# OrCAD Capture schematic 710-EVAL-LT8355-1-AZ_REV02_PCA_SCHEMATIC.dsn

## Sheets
1 PAGE2 - LT8355-1 CH2: size Custom; note: DEMO BOARD BILL OF MATERIALS; note: HIGH VOLTAGE DUAL LED CONTROLLER
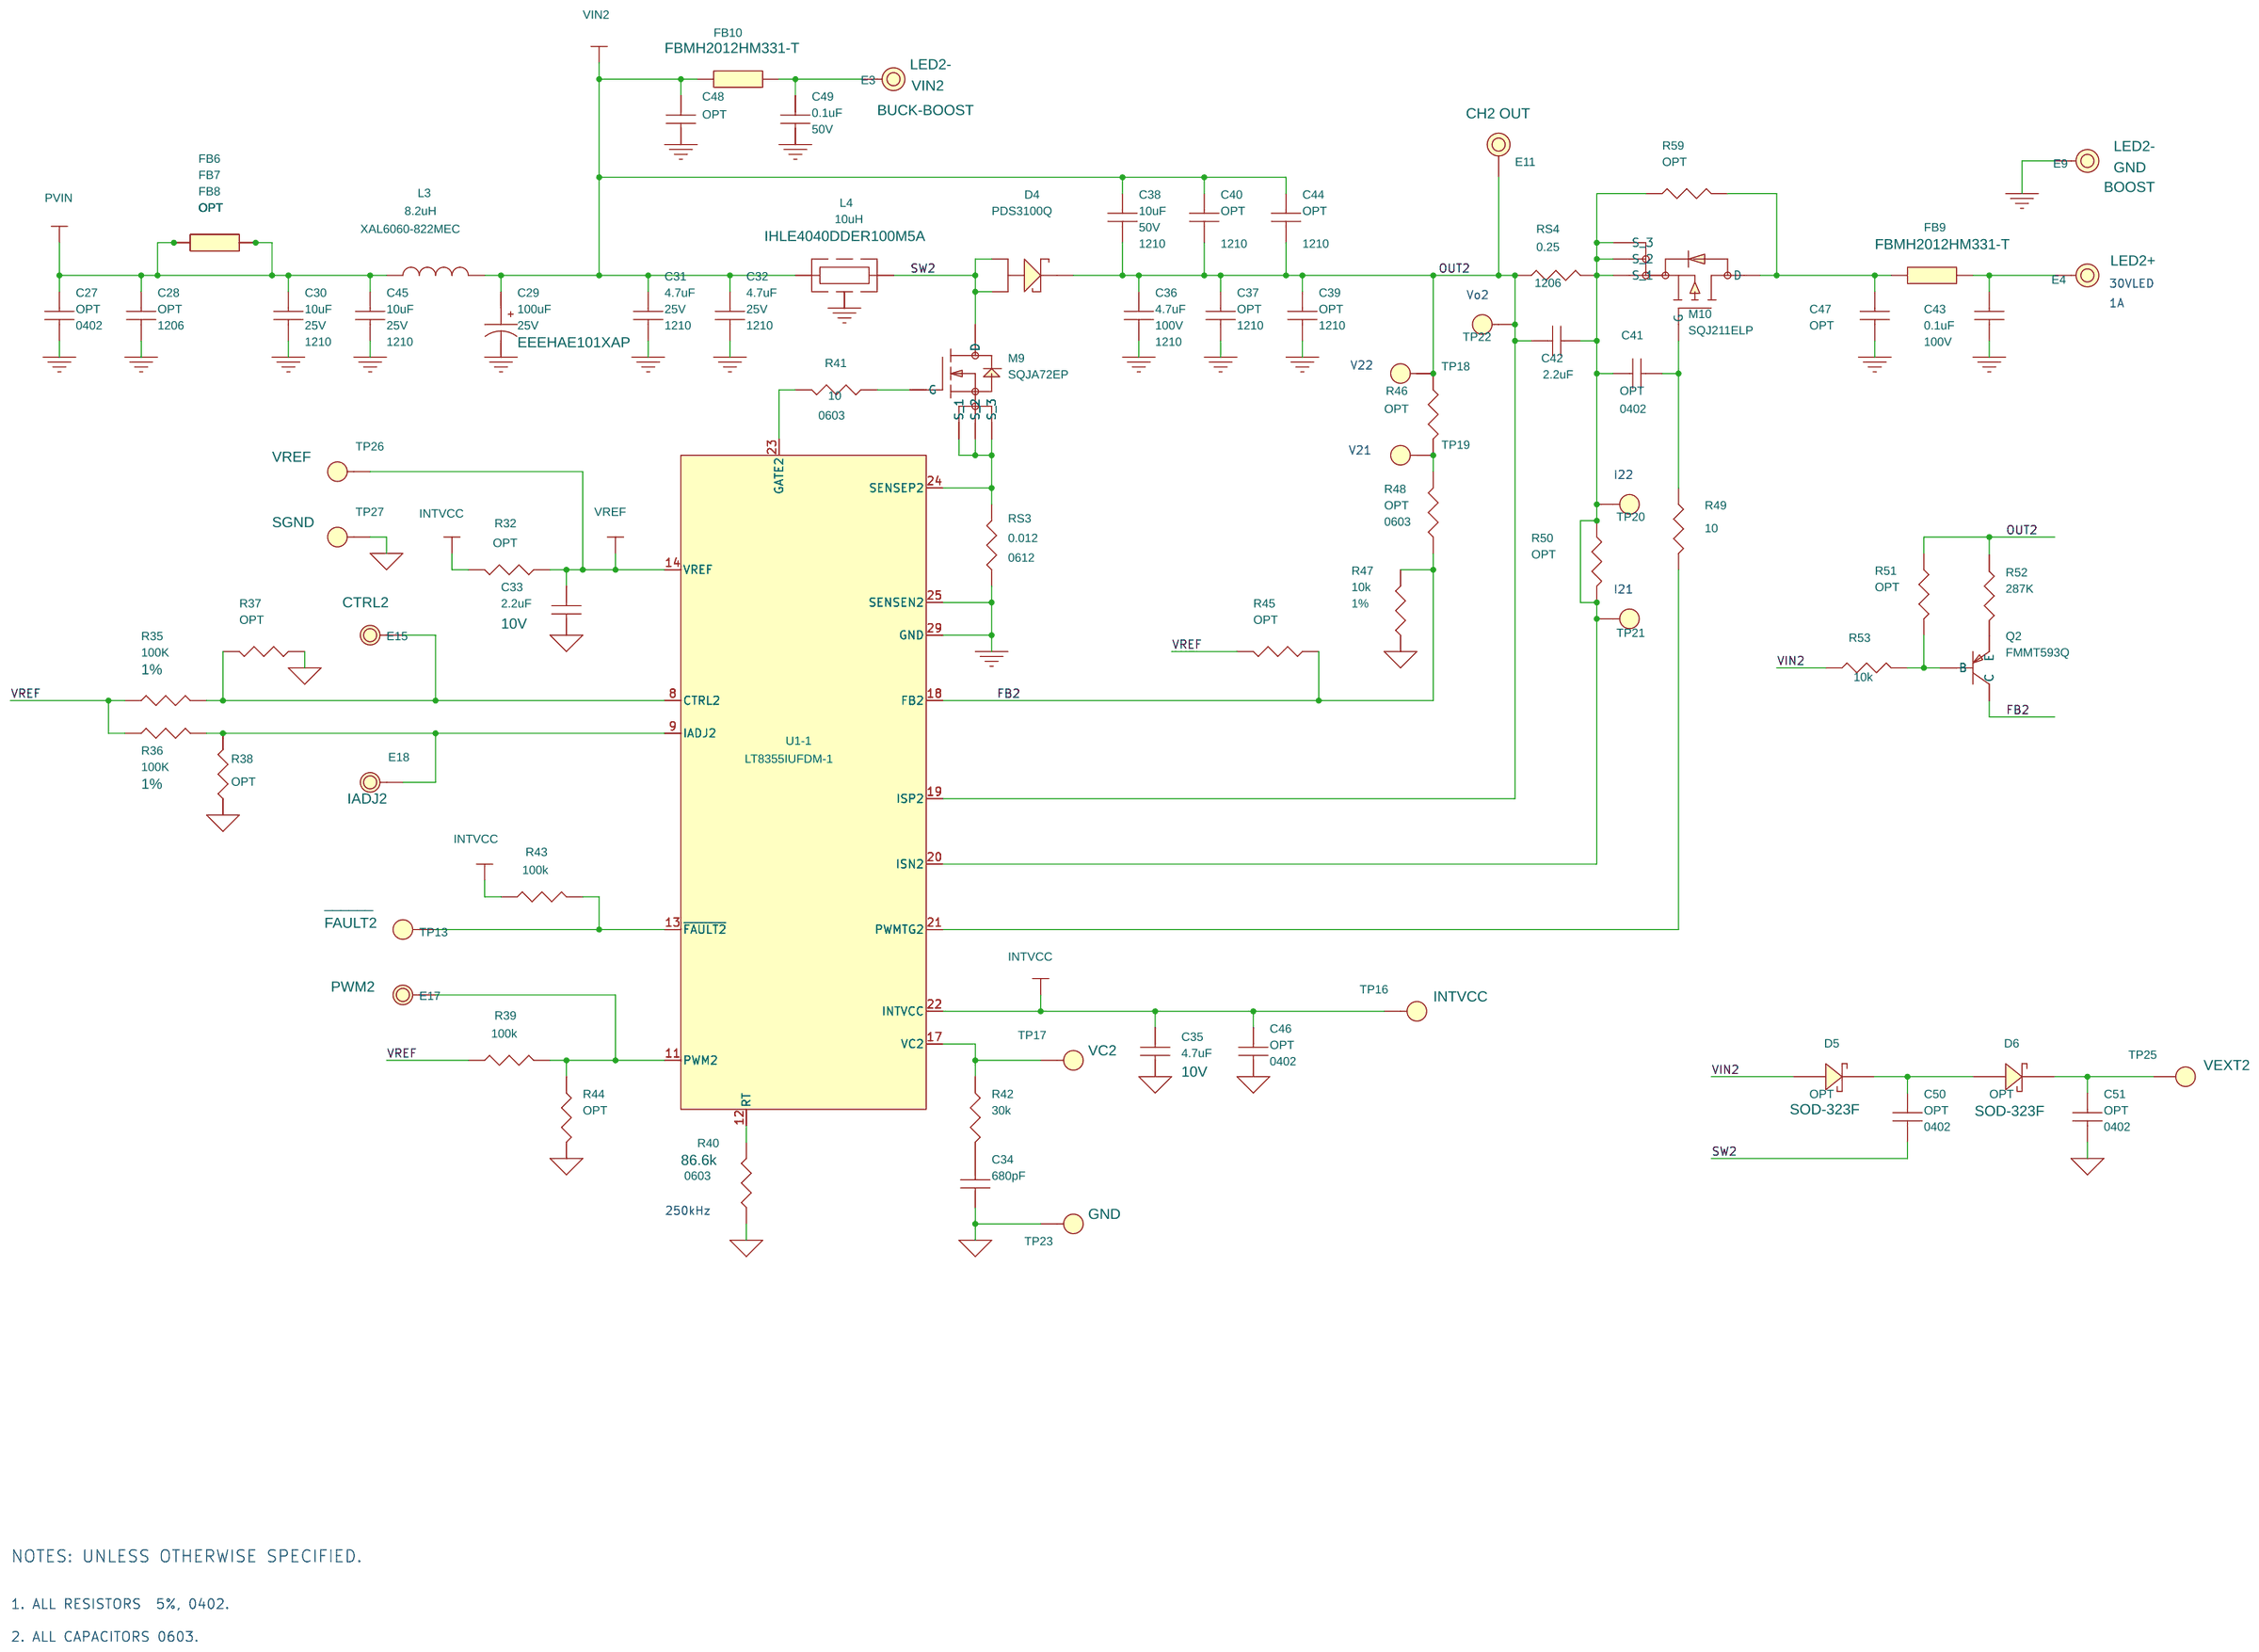
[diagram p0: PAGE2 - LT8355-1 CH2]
2 PAGE3 - HW
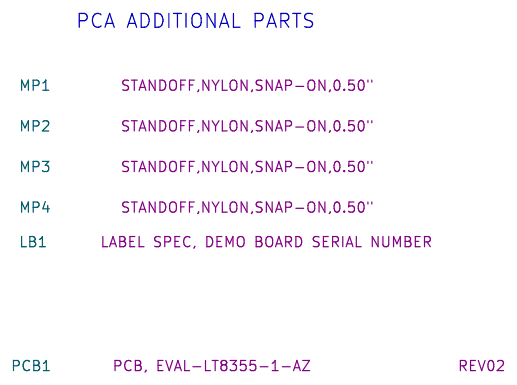
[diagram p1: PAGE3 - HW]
3 PAGE1 - LT8355-1 CH1: size Custom
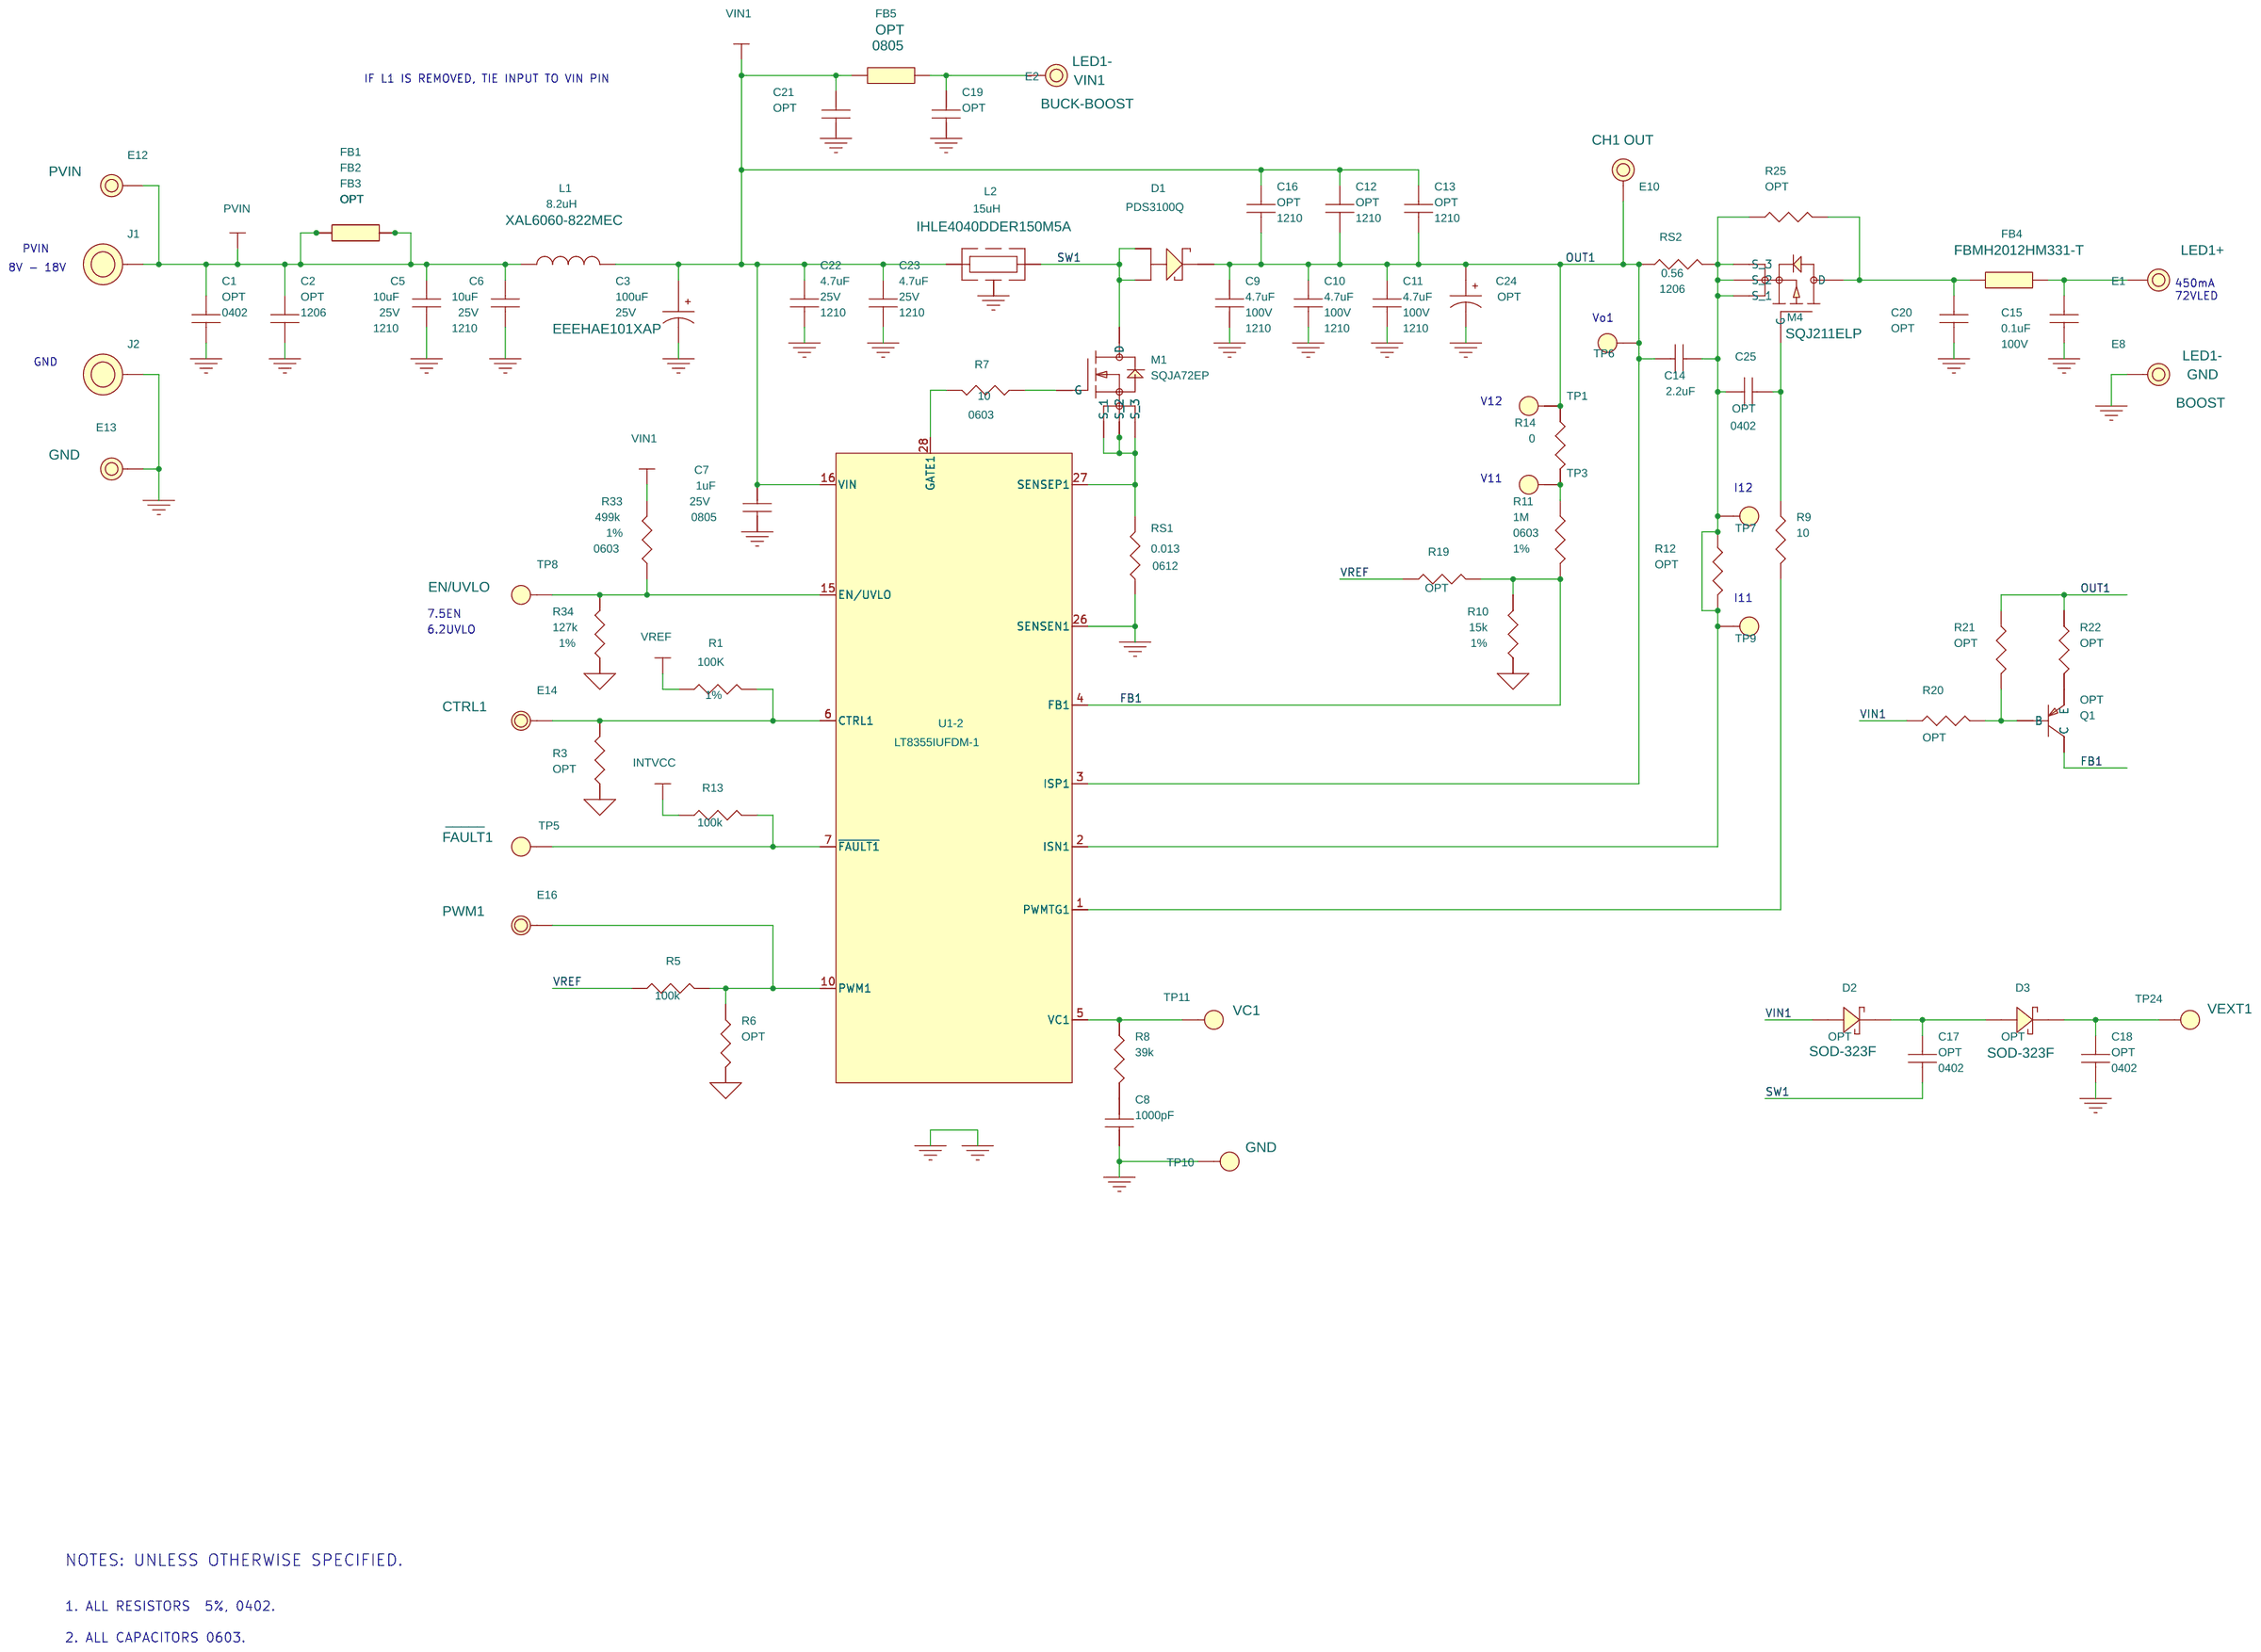
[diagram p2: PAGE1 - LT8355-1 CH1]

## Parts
sheet PAGE1 - LT8355-1 CH1
C1  OPT  [CC0402N]
C2  OPT  [CC1206N]
C3  100uF  [PANASONIC_HA_6.3X7.7]
C5  10uF  [CC1210N]
C6  10uF  [CC1210N]
C7  1uF  [CC0805N]
C8  1000pF  [CC0402N]
C9  4.7uF  [CC1210N]
C10  4.7uF  [CC1210N]
C11  4.7uF  [CC1210N]
C12  OPT  [CC1210N]
C13  OPT  [CC1210N]
C14  2.2uF  [CC0603N]
C15  0.1uF  [CC0603N]
C16  OPT  [CC1210N]
C17  OPT  [CC0402N]
C18  OPT  [CC0402N]
C19  OPT  [CC0603N]
C20  OPT  [CC0603N]
C21  OPT  [CC0603N]
C22  4.7uF  [CC1210N]
C23  4.7uF  [CC1210N]
C24  OPT  [CAP_OPT_8]
C25  OPT  [CC0402N]
D1  PDS3100Q  [POWERDI-5]
D2  OPT  [SOD-323F-N]
D3  OPT  [SOD-323F-N]
E1  TEST POINT  [MILLMAX2501]
E2  TEST POINT  [MILLMAX2501]
E8  TEST POINT  [MILLMAX2501]
E10  TEST POINT  [MILLMAX2501]
E12  TEST POINT  [MILLMAX2501]
E13  TEST POINT  [MILLMAX2501]
E14  TEST POINT  [MILLMAX2308]
E16  TEST POINT  [MILLMAX2308]
FB1  OPT  [IND1210N]
FB2  OPT  [IND1210N]
FB3  OPT  [IND1210N]
FB4  330 OHMS@100MHz  [IND0805N]
FB5  OPT  [IND0805N]
J1  BANANA JACK  [KEY-575-4]
J2  BANANA JACK  [KEY-575-4]
L1  8.2uH  [COILCRAFT-XAL6060]
L2  15uH  [VISHAY-IHLE-4040DD-5A]
M1  SQJA72EP  [VISHAY_PPAK-SO-8L]
M4  SQJ211ELP  [VISHAY_PPAK-SO-8L]
Q1  OPT  [SOT23-3N]
R1  100K  [CR0402N]
R3  OPT  [CR0402N]
R5  100k  [CR0402N]
R6  OPT  [CR0402N]
R7  10  [CR0603N]
R8  39k  [CR0402N]
R9  10  [CR0402N]
R10  15k  [CR0402N]
R11  1M  [CR0603N]
R12  OPT  [CR0402N]
R13  100k  [CR0402N]
R14  0  [CR0402N]
R19  OPT  [CR0402N]
R20  OPT  [CR0402N]
R21  OPT  [CR0402N]
R22  OPT  [CR0402N]
R25  OPT  [CR0402N]
R33  499k  [CR0603N]
R34  127k  [CR0402N]
RS1  0.013  [ROHM-LTR18]
RS2  0.56  [CR1206N]
TP1  TEST PAD  [PADSTYLE1]
TP3  TEST PAD  [PADSTYLE1]
TP5  TEST PAD  [PADSTYLE1]
TP6  TEST PAD  [PADSTYLE1]
TP7  TEST PAD  [PADSTYLE1]
TP8  TEST PAD  [PADSTYLE1]
TP9  TEST PAD  [PADSTYLE1]
TP10  TEST PAD  [PADSTYLE1]
TP11  TEST PAD  [PADSTYLE1]
TP24  TEST PAD  [PADSTYLE1]
sheet PAGE2 - LT8355-1 CH2
C27  OPT  [CC0402N]
C28  OPT  [CC1206N]
C29  100uF  [PANASONIC_HA_6.3X7.7]
C30  10uF  [CC1210N]
C31  4.7uF  [CC1210N]
C32  4.7uF  [CC1210N]
C33  2.2uF  [CC0603N]
C34  680pF  [CC0402N]
C35  4.7uF  [CC0603N]
C36  4.7uF  [CC1210N]
C37  OPT  [CC1210N]
C38  10uF  [CC1210N]
C39  OPT  [CC1210N]
C40  OPT  [CC1210N]
C41  OPT  [CC0402N]
C42  2.2uF  [CC0603N]
C43  0.1uF  [CC0603N]
C44  OPT  [CC1210N]
C45  10uF  [CC1210N]
C46  OPT  [CC0402N]
C47  OPT  [CC0603N]
C48  OPT  [CC0603N]
C49  0.1uF  [CC0603N]
C50  OPT  [CC0402N]
C51  OPT  [CC0402N]
D4  PDS3100Q  [POWERDI-5]
D5  OPT  [SOD-323F-N]
D6  OPT  [SOD-323F-N]
E3  TEST POINT  [MILLMAX2501]
E4  TEST POINT  [MILLMAX2501]
E9  TEST POINT  [MILLMAX2501]
E11  TEST POINT  [MILLMAX2501]
E15  TEST POINT  [MILLMAX2308]
E17  TEST POINT  [MILLMAX2308]
E18  TEST POINT  [MILLMAX2308]
FB6  OPT  [IND1210N]
FB7  OPT  [IND1210N]
FB8  OPT  [IND1210N]
FB9  330 OHMS@100MHz  [IND0805N]
FB10  330 OHMS@100MHz  [IND0805N]
L3  8.2uH  [COILCRAFT-XAL6060]
L4  10uH  [VISHAY-IHLE-4040DD-5A]
M9  SQJA72EP  [VISHAY_PPAK-SO-8L]
M10  SQJ211ELP  [VISHAY_PPAK-SO-8L]
Q2  FMMT593Q  [SOT23-3N]
R32  OPT  [CR0402N]
R35  100K  [CR0402N]
R36  100K  [CR0402N]
R37  OPT  [CR0402N]
R38  OPT  [CR0402N]
R39  100k  [CR0402N]
R40  86.6k  [CR0603N]
R41  10  [CR0603N]
R42  30k  [CR0402N]
R43  100k  [CR0402N]
R44  OPT  [CR0402N]
R45  OPT  [CR0402N]
R46  OPT  [CR0402N]
R47  10k  [CR0402N]
R48  OPT  [CR0603N]
R49  10  [CR0402N]
R50  OPT  [CR0402N]
R51  OPT  [CR0402N]
R52  287K  [CR0402N]
R53  10k  [CR0402N]
R59  OPT  [CR0402N]
RS3  0.012  [KOA-WU73-2B15]
RS4  0.25  [CR1206N]
TP13  TEST PAD  [PADSTYLE1]
TP16  TEST PAD  [PADSTYLE1]
TP17  TEST PAD  [PADSTYLE1]
TP18  TEST PAD  [PADSTYLE1]
TP19  TEST PAD  [PADSTYLE1]
TP20  TEST PAD  [PADSTYLE1]
TP21  TEST PAD  [PADSTYLE1]
TP22  TEST PAD  [PADSTYLE1]
TP23  TEST PAD  [PADSTYLE1]
TP25  TEST PAD  [PADSTYLE1]
TP26  TEST PAD  [PADSTYLE1]
TP27  TEST PAD  [PADSTYLE1]
U1  LT8355IUFDM-1  [LTC-UFDM-28-1682]  (sections -1,-2)
sheet PAGE3 - HW
LB1  LABEL  [895-0154_REV01]
MP1  STANDOFF  [KEYSTONE_8829-8834]
MP2  STANDOFF  [KEYSTONE_8829-8834]
MP3  STANDOFF  [KEYSTONE_8829-8834]
MP4  STANDOFF  [KEYSTONE_8829-8834]
PCB1  PCB, EVAL-LT8355-1-AZ

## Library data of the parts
C1 C17 C18 C25 C27 C41 C46 C50 C51 = CAP: CAP., OPTION, 0402; CLASS: DISCRETE; FPLIST: CC0402N,CC0402L,CC0402M; PART_NUMBER: 150-3148; Package Size: 0402; Package Type: SMD
C2 C28 = CAP: CAP., OPTION, 1206; CLASS: DISCRETE; FPLIST: CC1206N,CC1206L,CC1206M; PART_NUMBER: 150-3160; Package Size: 1206; Package Type: SMD
C3 C29 = CAP_P_ALT: CAP.,100uF,ALUM ELECT,25V,20%,,6.3x7.7mm,D8,SMD,RADIAL,EEEHA,AEC-Q200; CLASS: DISCRETE; Dielectric Type: ALUM ELECT; Inventory Qty: 0; Manufacturer: PANASONIC; Manufacturer PN: EEEHAE101XAP; PART_NUMBER: 150-1898; Package Size: ,6.3x7.7mm,D8,SMD,RADIAL; Rated Voltage: 25V; Tolerance: 20%
C5 C6 C30 C45 = CAP: CAP.,10uF,X7R,25V,10%,1210,AEC-Q200; CLASS: DISCRETE; Dielectric Type: X7R; FPLIST: CC1210N,CC1210L,CC1210M; Inventory Qty: 0; Manufacturer: TDK; Manufacturer PN: CGA6P1X7R1E106K250AC; PART_NUMBER: 150-1852; Package Size: 1210; Rated Voltage: 25V; Temperature Coefficient: X7R; Tolerance: 10%
C7 = CAP: CAP.,1uF,X7R,25V,10%,0805,AEC-Q200; CLASS: DISCRETE; Dielectric Type: X7R; FPLIST: CC0805N,CC0805L,CC0805M; Inventory Qty: 1975; Manufacturer: TDK; Manufacturer PN: CGA4J3X7R1E105K125AB; PART_NUMBER: 150-0504; Package Size: 0805; Rated Voltage: 25V; Tolerance: 10%
C8 = CAP: CAP.,1000pF,X7R,50V,10%,0402,AEC-Q200; CLASS: DISCRETE; Dielectric Type: X7R; FPLIST: CC0402N,CC0402L,CC0402M; Inventory Qty: 12960; Manufacturer: MURATA; Manufacturer PN: GCM155R71H102KA37D; PART_NUMBER: 150-1752; Package Size: 0402; Package Type: SMD; Rated Voltage: 50V; Tolerance: 10%
C9-C11 C36 = CAP: CAP.,4.7uF,X7S,100V,10%,1210,AEC-Q200; CLASS: DISCRETE; Dielectric Type: X7S; FPLIST: CC1210N,CC1210L,CC1210M; Inventory Qty: 14180; Manufacturer: MURATA; Manufacturer PN: GCM32DC72A475KE02L; PART_NUMBER: 150-3376; Package Size: 1210; Rated Voltage: 100V; Tolerance: 10%
C12 C13 C16 C37 C39 C40 C44 = CAP: CAP., OPTION, 1210; CLASS: DISCRETE; FPLIST: CC1210N,CC1210L,CC1210M; PART_NUMBER: 150-3035; Package Size: 1210; Package Type: SMD
C14 C42 = CAP: CAP.,2.2uF,X5R,25V,10%,0603,AEC-Q200; CLASS: DISCRETE; Dielectric Type: X5R; FPLIST: CC0603N,CC0603L,CC0603M; Inventory Qty: 0; Manufacturer: TAIYO YUDEN; Manufacturer PN: TMK107BBJ225KAHT; PART_NUMBER: 150-0955; Package Size: 0603; Rated Voltage: 25V; Tolerance: 10%
C15 C43 = CAP: CAP.,0.1uF,X7S,100V,10%,0603,AEC-Q200; CLASS: DISCRETE; Dielectric Type: X7S; FPLIST: CC0603N,CC0603L,CC0603M; Inventory Qty: 27710; Manufacturer: TDK; Manufacturer PN: CGA3E3X7S2A104K080AB; PART_NUMBER: 150-2322; Package Size: 0603; Rated Voltage: 100V; Tolerance: 10%
C19-C21 C47 C48 = CAP: CAP., OPTION, 0603; CLASS: DISCRETE; FPLIST: CC0603N,CC0603L,CC0603M; PART_NUMBER: 150-3038; Package Size: 0603; Package Type: SMD
C22 C23 C31 C32 = CAP: CAP.,4.7uF,X7R,25V,10%,1210,AEC-Q200; CLASS: DISCRETE; Dielectric Type: X7R; FPLIST: CC1210N,CC1210L,CC1210M; Inventory Qty: 0; Manufacturer: Taiyo Yuden; Manufacturer PN: TMF325B7475KMHP; PART_NUMBER: 150-1899; Package Size: 1210; Package Type: SMD; Rated Voltage: 25V; Tolerance: 10%
C24 = CAP_P_ALT: CAP.,OPTION,ALUM. ELECT.,SMD; CLASS: DISCRETE; FPLIST: USER_ASSIGNED,USER_1,USER_2,USER_3,USER_4,USER_5,USER_6,USER_7,CAP_OPT_6.3,CAP_OPT_8,CAP_OPT_10,CAP_OPT_12.5,CAP_OPT_13,CAP_OPT_16,CAP_OPT_18; PART_NUMBER: 150-0497; Package Type: SMD
D1 D4 = DIODE_SCHOTTKY_POWERDI5: DIODE,SCHOTTKY,100V,3A,POWERDI5,AEC-Q101; CLASS: DISCRETE; FPLIST: POWERDI-5,POWERDI-5_2PIN; Inventory Qty: 0; Manufacturer: DIODES INC.; Manufacturer PN: PDS3100Q-13; Max Forward Current or Rated Power: 3A; PART_NUMBER: 210-0596; Package Type: PowerDI5; Rated Voltage or Zener Voltage: 100V
D2 D3 D5 D6 = DIODE_SCHOTTKY_A_ALT: DIODE,OPTION, SOD-323F; BOM Notes: BAT46WJ; CLASS: DISCRETE; FPLIST: SOD-323F-N,SOD-323F-L,SOD-323F-M; PART_NUMBER: 210-0458; Package Size: SOD-323F; Package Type: SOD323F-2
E1 = TESTPOINT_.219_MILL-MAX_2501: TEST POINT,TURRET,0.094" MTG. HOLE,PCB 0.062" THK; 10th Part Field: TURN+; 11th Part Field: 52V OVLO; 12th Part Field: 60V MAX.; 9th Part Field: LED1+; CLASS: IO; FPLIST: MILLMAX2501,MILLMAX2501-2; Inventory Qty: 823526; Manufacturer: MILL-MAX; Manufacturer PN: 2501-2-00-80-00-00-07-0; PART_NUMBER: 260-0003
E2 = TESTPOINT_.219_MILL-MAX_2501: TEST POINT,TURRET,0.094" MTG. HOLE,PCB 0.062" THK; 10th Part Field: VIN1; 11th Part Field: BUCK-BOOST; 12th Part Field: 60V MAX.; 9th Part Field: LED1-; CLASS: IO; FPLIST: MILLMAX2501,MILLMAX2501-2; Inventory Qty: 823526; Manufacturer: MILL-MAX; Manufacturer PN: 2501-2-00-80-00-00-07-0; PART_NUMBER: 260-0003
E8 = TESTPOINT_.219_MILL-MAX_2501: TEST POINT,TURRET,0.094" MTG. HOLE,PCB 0.062" THK; 10th Part Field: GND; 11th Part Field: BOOST; 12th Part Field: 60V MAX.; 9th Part Field: LED1-; CLASS: IO; FPLIST: MILLMAX2501,MILLMAX2501-2; Inventory Qty: 823526; Manufacturer: MILL-MAX; Manufacturer PN: 2501-2-00-80-00-00-07-0; PART_NUMBER: 260-0003
E10 = TESTPOINT_.219_MILL-MAX_2501: TEST POINT,TURRET,0.094" MTG. HOLE,PCB 0.062" THK; 10th Part Field: CH1 OUT; 11th Part Field: CH1 OUT; 12th Part Field: CH1 OUT; 9th Part Field: CH1 OUT; CLASS: IO; FPLIST: MILLMAX2501,MILLMAX2501-2; Inventory Qty: 823526; Manufacturer: MILL-MAX; Manufacturer PN: 2501-2-00-80-00-00-07-0; PART_NUMBER: 260-0003
E12 = TESTPOINT_.219_MILL-MAX_2501: TEST POINT,TURRET,0.094" MTG. HOLE,PCB 0.062" THK; 10th Part Field: TURN+; 11th Part Field: 52V OVLO; 12th Part Field: 60V MAX.; 9th Part Field: PVIN; CLASS: IO; FPLIST: MILLMAX2501,MILLMAX2501-2; Inventory Qty: 823526; Manufacturer: MILL-MAX; Manufacturer PN: 2501-2-00-80-00-00-07-0; PART_NUMBER: 260-0003
E13 = TESTPOINT_.219_MILL-MAX_2501: TEST POINT,TURRET,0.094" MTG. HOLE,PCB 0.062" THK; 10th Part Field: GND; 11th Part Field: 52V OVLO; 12th Part Field: 60V MAX.; 9th Part Field: GND; CLASS: IO; FPLIST: MILLMAX2501,MILLMAX2501-2; Inventory Qty: 823526; Manufacturer: MILL-MAX; Manufacturer PN: 2501-2-00-80-00-00-07-0; PART_NUMBER: 260-0003
E14 = TEST_POINT_.156_MILL-MAX_2308_A: TEST POINT,TURRET,0.064" MTG. HOLE,PCB 0.062" THK; 9th Part Field: CTRL1; CLASS: IO; FPLIST: MILLMAX2308,MILLMAX2308-2; Inventory Qty: 1142083; Manufacturer: MILL-MAX; Manufacturer PN: 2308-2-00-80-00-00-07-0; PART_NUMBER: 260-0004
E16 = TEST_POINT_.156_MILL-MAX_2308_A: TEST POINT,TURRET,0.064" MTG. HOLE,PCB 0.062" THK; 9th Part Field: PWM1; CLASS: IO; FPLIST: MILLMAX2308,MILLMAX2308-2; Inventory Qty: 1142083; Manufacturer: MILL-MAX; Manufacturer PN: 2308-2-00-80-00-00-07-0; PART_NUMBER: 260-0004
FB1-FB3 FB6-FB8 = FERRITEBEAD_ALT1: IND.,OPTION,FERRITE BEAD,1210; CLASS: DISCRETE; FPLIST: IND1210N,IND1210L,IND1210M; PART_NUMBER: 200-0785; Package Size: 1210
FB4 FB9 FB10 = FERRITEBEAD_ALT1: IND.,330 OHMS@100MHz,FERRITE BEAD,25%,1.8A,80mOHMS,0805,1LN; CLASS: DISCRETE; FPLIST: IND0805N,IND0805L,IND0805M; Inventory Qty: 4000; Manufacturer: TAIYO YUDEN; Manufacturer PN: FBMH2012HM331-T; PART_NUMBER: 200-0778; Package Size: 0805; Tolerance: 25%
FB5 = FERRITEBEAD_ALT1: IND.,FERRITE BEAD,OPT,0805; CLASS: DISCRETE; FPLIST: IND0805N,IND0805L,IND0805M; PART_NUMBER: 200-0529; Package Size: 0805
J1 J2 = BANANA_KEYSTONE-575-4: CONN.,BANANA JACK,FEMALE,THT,NON-INSULATED,SWAGE,0.218"; CLASS: IO; Inventory Qty: 203061; Manufacturer: KEYSTONE; Manufacturer PN: 575-4; PART_NUMBER: 250-0428
L1 L3 = IND: IND.,8.2uH,PWR,SHIELDED,20%,8A,26.4mOHMS,6.56x6.36mm,XAL6060,AEC-Q200; CLASS: DISCRETE; Inventory Qty: 0; Manufacturer: COILCRAFT; Manufacturer PN: XAL6060-822MEC; PART_NUMBER: 200-0920; Package Size: 6.56x6.36mm,XAL6060; Tolerance: 20%
L2 = IND_4-PIN_SHIELDED: IND.,15uH,PWR,SHIELDED,20%,7.7A,50.29mOHMS,4040DD,IHLE-5A,AEC-Q200; CLASS: DISCRETE; Inventory Qty: 0; Manufacturer: VISHAY; Manufacturer PN: IHLE4040DDER150M5A; PART_NUMBER: 200-0921; Package Size: 4040DD; Tolerance: 20%
M1 = 5P_N-CH_TYPE1D: XSTR.,MOSFET,N-CH,100V,37A,PowerPAK SO-8L,AEC-Q101; CLASS: DISCRETE; Inventory Qty: 0; Manufacturer: VISHAY; Manufacturer PN: SQJA72EP-T1_GE3; PART_NUMBER: 240-0565; Package Type: PowerPAK SO-8L; Rated Voltage: 100V
M4 = 5P_P-CH_TYPE1D: XSTR.,MOSFET,P-CH,100V,33.6A,PowerPAK SO-8L,AEC-Q101; CLASS: DISCRETE; Inventory Qty: 0; Manufacturer: VISHAY; Manufacturer PN: SQJ211ELP-T1_GE3; PART_NUMBER: 240-0610; Package Size: PowerPAK SO-8; Package Type: PowerPAK SO-8L; Polarity: P Channel; Rated Voltage: 100V
Q1 = 3P_PNP_TYPE1A: XSTR., OPTION, PNP, SOT-23; CLASS: DISCRETE; FPLIST: SOT23-3N,SOT23-3L,SOT23-3M; PART_NUMBER: 240-0127; Package Type: SOT-23
R1 R35 R36 = RES: RES.,100k OHMS,1%,1/16W,0402,AEC-Q200; CLASS: DISCRETE; FPLIST: CR0402N,CR0402L,CR0402M; Inventory Qty: 92256; Manufacturer: NIC; Manufacturer PN: NRC04F1003TRF; PART_NUMBER: 100-0601; Package Size: 0402; Rated Power: 1/16W; Temperature Coefficient: 100PPM; Tolerance: 1%
R3 R6 R12 R19-R22 R25 R32 R37 R38 R44-R46 R50 R51 R59 = RES: RES., OPTION, 0402; CLASS: DISCRETE; FPLIST: CR0402N,CR0402L,CR0402M; PART_NUMBER: 100-0357; Package Size: 0402
R5 R13 R39 R43 = RES: RES.,100k OHMS,5%,1/16W,0402,AEC-Q200; CLASS: DISCRETE; FPLIST: CR0402N,CR0402L,CR0402M; Inventory Qty: 59032; Manufacturer: NIC; Manufacturer PN: NRC04J104TRF; PART_NUMBER: 100-0359; Package Size: 0402; Rated Power: 1/16W; Temperature Coefficient: 200ppm/C; Tolerance: 5%
R7 R41 = RES: RES.,10 OHMS,5%,1/10W,0603,AEC-Q200; CLASS: DISCRETE; FPLIST: CR0603N,CR0603L,CR0603M; Inventory Qty: 57688; Manufacturer: PANASONIC; Manufacturer PN: ERJ3GEYJ100V; PART_NUMBER: 100-2058; Package Size: 0603; Rated Power: 1/10W; Temperature Coefficient: 200ppm/C; Tolerance: 5%
R8 = RES: RES.,39k OHMS,1%,1/16W,0402,AEC-Q200; CLASS: DISCRETE; FPLIST: CR0402N,CR0402L,CR0402M; Manufacturer: YAGEO; Manufacturer PN: AC0402FR-0739KL; PART_NUMBER: 100-1932; Package Size: 0402; Rated Power: 1/16W; Temperature Coefficient: +/-100ppm; Tolerance: 1%
R9 R49 = RES: RES.,10 OHMS,5%,1/16W,0402,AEC-Q200; CLASS: DISCRETE; FPLIST: CR0402N,CR0402L,CR0402M; Inventory Qty: 18730; Manufacturer: VISHAY; Manufacturer PN: CRCW040210R0JNED; PART_NUMBER: 100-1227; Package Size: 0402; Rated Power: 1/16W; Temperature Coefficient: +/-200ppm; Tolerance: 5%
R10 = RES: RES.,15k OHMS,1%,1/16W,0402,AEC-Q200; CLASS: DISCRETE; FPLIST: CR0402N,CR0402L,CR0402M; Inventory Qty: 0; Manufacturer: YAGEO; Manufacturer PN: AC0402FR-0715KL; PART_NUMBER: 100-1868; Package Size: 0402; Rated Power: 1/16W; Temperature Coefficient: +/-100ppm; Tolerance: 1%
R11 = RES: RES.,1M OHM,1%,1/10W,0603; CLASS: DISCRETE; FPLIST: CR0603N,CR0603L,CR0603M; Inventory Qty: 165718; Manufacturer: VISHAY; Manufacturer PN: CRCW06031M00FKEA; PART_NUMBER: 100-0335; Package Size: 0603; Rated Power: 1/10W; Temperature Coefficient: 100ppm; Tolerance: 1%
R14 = RES: RES.,0 OHM,1/10W,0402,AEC-Q200; CLASS: DISCRETE; FPLIST: CR0402N,CR0402L,CR0402M; Inventory Qty: 32994; Manufacturer: PANASONIC; Manufacturer PN: ERJ2GE0R00X; PART_NUMBER: 100-2408; Package Size: 0402; Rated Power: 1/10W
R33 = RES: RES.,499k OHMS,1%,1/10W,0603,AEC-Q200; CLASS: DISCRETE; FPLIST: CR0603N,CR0603L,CR0603M; Inventory Qty: 58967; Manufacturer: VISHAY; Manufacturer PN: CRCW0603499KFKEA; PART_NUMBER: 100-0122; Package Size: 0603; Rated Power: 1/10W; Temperature Coefficient: 100ppm/C; Tolerance: 1%
R34 = RES: RES.,127k OHMS,1%,1/16W,0402,AEC-Q200; CLASS: DISCRETE; FPLIST: CR0402N,CR0402L,CR0402M; Inventory Qty: 0; Manufacturer: VISHAY; Manufacturer PN: CRCW0402127KFKED; PART_NUMBER: 100-2516; Package Size: 0402; Rated Power: 1/16W; Temperature Coefficient: 100ppm/C; Tolerance: 1%
RS1 = RES: RES.,0.013 OHM,1%,1W,1206,LONG-SIDE TERM,SENSE,AEC-Q200; 9th Part Field: 0612; CLASS: DISCRETE; Inventory Qty: 0; Manufacturer: ROHM; Manufacturer PN: LTR18EZPFSR013; PART_NUMBER: 100-1933; Package Size: 1206,LONG-SIDE TERM; Rated Power: 1W; Temperature Coefficient: 0/+300ppm; Tolerance: 1%
RS2 = RES: RES.,0.56 OHM,1%,1/2W,1206,SENSE,AEC-Q200; CLASS: DISCRETE; FPLIST: CR1206N,CR1206L,CR1206M; Inventory Qty: 0; Manufacturer: PANASONIC; Manufacturer PN: ERJ8BQFR56V; PART_NUMBER: 100-1925; Package Size: 1206; Rated Power: 1/2W; Temperature Coefficient: +/-250ppm; Tolerance: 1%
TP1 TP3 TP6-TP9 TP18-TP22 = PAD_STYLE_C: TESTPOINT, PCB COPPER FEATURE; 10th Part Field: ______; 9th Part Field: EN/UVLO; CLASS: IO; FPLIST: PADSTYLE1,PADSTYLE2,PADSTYLE3,PADSTYLE4,PADSTYLE5,PADSTYLE6,PADSTYLE7,PADSTYLE8; Manufacturer: N/A; Manufacturer PN: N/A
TP5 = PAD_STYLE_C: TESTPOINT, PCB COPPER FEATURE; 10th Part Field: _____; 9th Part Field: FAULT1; CLASS: IO; FPLIST: PADSTYLE1,PADSTYLE2,PADSTYLE3,PADSTYLE4,PADSTYLE5,PADSTYLE6,PADSTYLE7,PADSTYLE8; Manufacturer: N/A; Manufacturer PN: N/A
TP10 TP23 = PAD_STYLE_C: TESTPOINT, PCB COPPER FEATURE; 10th Part Field: ______; 9th Part Field: GND; CLASS: IO; FPLIST: PADSTYLE1,PADSTYLE2,PADSTYLE3,PADSTYLE4,PADSTYLE5,PADSTYLE6,PADSTYLE7,PADSTYLE8; Manufacturer: N/A; Manufacturer PN: N/A
TP11 = PAD_STYLE_C: TESTPOINT, PCB COPPER FEATURE; 9th Part Field: VC1; CLASS: IO; FPLIST: PADSTYLE1,PADSTYLE2,PADSTYLE3,PADSTYLE4,PADSTYLE5,PADSTYLE6,PADSTYLE7,PADSTYLE8; Manufacturer: N/A; Manufacturer PN: N/A
TP24 = PAD_STYLE_C: TESTPOINT, PCB COPPER FEATURE; 9th Part Field: VEXT1; CLASS: IO; FPLIST: PADSTYLE1,PADSTYLE2,PADSTYLE3,PADSTYLE4,PADSTYLE5,PADSTYLE6,PADSTYLE7,PADSTYLE8; Manufacturer: N/A; Manufacturer PN: N/A
C33 = CAP: CAP.,2.2uF,X5R,10V,10%,0603,AEC-Q200; CLASS: DISCRETE; Dielectric Type: X5R; FPLIST: CC0603N,CC0603L,CC0603M; Inventory Qty: 0; Manufacturer: TAIYO YUDEN; Manufacturer PN: LMK107BJ225KAHT; PART_NUMBER: 150-1880; Package Size: 0603; Rated Voltage: 10V; Tolerance: 10%
C34 = CAP: CAP.,680pF,X7R,50V,10%,0402,AEC-Q200; CLASS: DISCRETE; Dielectric Type: X7R; FPLIST: CC0402N,CC0402L,CC0402M; Inventory Qty: 0; Manufacturer: TDK; Manufacturer PN: CGA2B2X7R1H681K050BA; PART_NUMBER: 150-1013; Package Size: 0402; Rated Voltage: 50V; Tolerance: 10%
C35 = CAP: CAP.,4.7uF,X5R,10V,10%,0603,AEC-Q200; CLASS: DISCRETE; Dielectric Type: X5R; FPLIST: CC0603N,CC0603L,CC0603M; Inventory Qty: 4000; Manufacturer: Taiyo Yuden; Manufacturer PN: LMK107BJ475KAHT; PART_NUMBER: 150-1819; Package Size: 0603; Rated Voltage: 10V; Temperature Coefficient: X5R; Tolerance: 10%
C38 = CAP: CAP.,10uF,X7S,50V,10%,1210,AEC-Q200, NO SUBS ALLOWED; CLASS: DISCRETE; Dielectric Type: X7S; FPLIST: CC1210N,CC1210L,CC1210M; Inventory Qty: 10520; Manufacturer: MURATA; Manufacturer PN: GCM32EC71H106KA03L; PART_NUMBER: 150-2354; Package Size: 1210; Rated Voltage: 50V; Tolerance: 10%
C49 = CAP: CAP.,0.1uF,X7R,50V,10%,0603,AEC-Q200; CLASS: DISCRETE; Dielectric Type: X7R; FPLIST: CC0603N,CC0603L,CC0603M; Inventory Qty: 20275; Manufacturer: TDK; Manufacturer PN: CGA3E2X7R1H104K080AA; PART_NUMBER: 150-0514; Package Size: 0603; Rated Voltage: 50V; Tolerance: 10%
E3 = TESTPOINT_.219_MILL-MAX_2501: TEST POINT,TURRET,0.094" MTG. HOLE,PCB 0.062" THK; 10th Part Field: VIN2; 11th Part Field: BUCK-BOOST; 12th Part Field: 60V MAX.; 9th Part Field: LED2-; CLASS: IO; FPLIST: MILLMAX2501,MILLMAX2501-2; Inventory Qty: 823526; Manufacturer: MILL-MAX; Manufacturer PN: 2501-2-00-80-00-00-07-0; PART_NUMBER: 260-0003
E4 = TESTPOINT_.219_MILL-MAX_2501: TEST POINT,TURRET,0.094" MTG. HOLE,PCB 0.062" THK; 10th Part Field: BOOST; 11th Part Field: 52V OVLO; 12th Part Field: 60V MAX.; 9th Part Field: LED2+; CLASS: IO; FPLIST: MILLMAX2501,MILLMAX2501-2; Inventory Qty: 823526; Manufacturer: MILL-MAX; Manufacturer PN: 2501-2-00-80-00-00-07-0; PART_NUMBER: 260-0003
E9 = TESTPOINT_.219_MILL-MAX_2501: TEST POINT,TURRET,0.094" MTG. HOLE,PCB 0.062" THK; 10th Part Field: GND; 11th Part Field: BOOST; 12th Part Field: 60V MAX.; 9th Part Field: LED2-; CLASS: IO; FPLIST: MILLMAX2501,MILLMAX2501-2; Inventory Qty: 823526; Manufacturer: MILL-MAX; Manufacturer PN: 2501-2-00-80-00-00-07-0; PART_NUMBER: 260-0003
E11 = TESTPOINT_.219_MILL-MAX_2501: TEST POINT,TURRET,0.094" MTG. HOLE,PCB 0.062" THK; 10th Part Field: CH2 OUT; 11th Part Field: CH2 OUT; 12th Part Field: CH2 OUT; 9th Part Field: CH2 OUT; CLASS: IO; FPLIST: MILLMAX2501,MILLMAX2501-2; Inventory Qty: 823526; Manufacturer: MILL-MAX; Manufacturer PN: 2501-2-00-80-00-00-07-0; PART_NUMBER: 260-0003
E15 = TEST_POINT_.156_MILL-MAX_2308_A: TEST POINT,TURRET,0.064" MTG. HOLE,PCB 0.062" THK; 9th Part Field: CTRL2; CLASS: IO; FPLIST: MILLMAX2308,MILLMAX2308-2; Inventory Qty: 1142083; Manufacturer: MILL-MAX; Manufacturer PN: 2308-2-00-80-00-00-07-0; PART_NUMBER: 260-0004
E17 = TEST_POINT_.156_MILL-MAX_2308_A: TEST POINT,TURRET,0.064" MTG. HOLE,PCB 0.062" THK; 9th Part Field: PWM2; CLASS: IO; FPLIST: MILLMAX2308,MILLMAX2308-2; Inventory Qty: 1142083; Manufacturer: MILL-MAX; Manufacturer PN: 2308-2-00-80-00-00-07-0; PART_NUMBER: 260-0004
E18 = TEST_POINT_.156_MILL-MAX_2308_A: TEST POINT,TURRET,0.064" MTG. HOLE,PCB 0.062" THK; 9th Part Field: IADJ2; CLASS: IO; FPLIST: MILLMAX2308,MILLMAX2308-2; Inventory Qty: 1142083; Manufacturer: MILL-MAX; Manufacturer PN: 2308-2-00-80-00-00-07-0; PART_NUMBER: 260-0004
L4 = IND_4-PIN_SHIELDED: IND.,10uH,PWR,SHIELDED,20%,8.5A,33.06mOHMS,4040DD,IHLE-5A Series,AEC-Q200; CLASS: DISCRETE; Inventory Qty: 1500; Manufacturer: VISHAY; Manufacturer PN: IHLE4040DDER100M5A; PART_NUMBER: 200-0820; Package Size: 4040DD; Tolerance: 20%
M9 = 5P_N-CH_TYPE1D: XSTR.,MOSFET,N-CH,100V,37A,PowerPAK SO-8L,AEC-Q101; CLASS: DISCRETE; FPLIST: VISHAY_PPAK-SO-8L,VISHAY_PPAK_SO-8L,POWERPAK_SO-8L; Inventory Qty: 0; Manufacturer: VISHAY; Manufacturer PN: SQJA72EP-T1_GE3; PART_NUMBER: 240-0565; Package Type: PowerPAK SO-8L; Rated Voltage: 100V
M10 = 5P_P-CH_TYPE1C: XSTR.,MOSFET,P-CH,100V,33.6A,PowerPAK SO-8L,AEC-Q101; CLASS: DISCRETE; Inventory Qty: 0; Manufacturer: VISHAY; Manufacturer PN: SQJ211ELP-T1_GE3; PART_NUMBER: 240-0610; Package Size: PowerPAK SO-8; Package Type: PowerPAK SO-8L; Polarity: P Channel; Rated Voltage: 100V
Q2 = 3P_PNP_TYPE1A: XSTR.,PNP,100V,1A,SOT-23-3,AEC-Q101; CLASS: DISCRETE; FPLIST: SOT23-3N,SOT23-3L,SOT23-3M; Inventory Qty: 0; Manufacturer: DIODES INC.; Manufacturer PN: FMMT593QTA; PART_NUMBER: 240-0611; Package Type: SOT-23-3; Rated Voltage: 100V
R40 = RES: RES.,86.6k OHMS,1%,1/10W,0603,AEC-Q200; 1st_Part_Field: 1%; CLASS: DISCRETE; FPLIST: CR0603N,CR0603L,CR0603M; Inventory Qty: 99354; Manufacturer: PANASONIC; Manufacturer PN: ERJ3EKF8662V; PART_NUMBER: 100-2711; Package Size: 0603; Rated Power: 1/10W; Temperature Coefficient: +/-100ppm; Tolerance: 1%
R42 = RES: RES.,30k OHMS,1%,1/16W,0402,AEC-Q200; CLASS: DISCRETE; FPLIST: CR0402N,CR0402L,CR0402M; Inventory Qty: 69690; Manufacturer: STACKPOLE ELECTRONICS, INC.; Manufacturer PN: RMCF0402FT30K0; PART_NUMBER: 100-0218; Package Size: 0402; Rated Power: 1/16W; Temperature Coefficient: 100ppm/C; Tolerance: 1%
R47 = RES: RES.,10k OHMS,1%,1/10W,0402,AEC-Q200; CLASS: DISCRETE; FPLIST: CR0402N,CR0402L,CR0402M; Inventory Qty: 88953; Manufacturer: KOA SPEER; Manufacturer PN: RK73H1ETTP1002F; PART_NUMBER: 100-0724; Package Size: 0402; Rated Power: 1/10W; Temperature Coefficient: 100ppm; Tolerance: 1%
R48 = RES: RES., OPTION, 0603; CLASS: DISCRETE; FPLIST: CR0603N,CR0603L,CR0603M; PART_NUMBER: 100-2374; Package Size: 0603
R52 = RES: RES.,287k OHMS,1%,1/16W,0402,AEC-Q200; CLASS: DISCRETE; FPLIST: CR0402N,CR0402L,CR0402M; Inventory Qty: 9860; Manufacturer: VISHAY; Manufacturer PN: CRCW0402287KFKED; PART_NUMBER: 100-2867; Package Size: 0402; Rated Power: 1/16W; Temperature Coefficient: 100PPM; Tolerance: 1%
R53 = RES: RES.,10k OHMS,5%,1/16W,0402,AEC-Q200; CLASS: DISCRETE; FPLIST: CR0402N,CR0402L,CR0402M; Inventory Qty: 64117; Manufacturer: NIC; Manufacturer PN: NRC04J103TRF; PART_NUMBER: 100-0214; Package Size: 0402; Rated Power: 1/16W; Temperature Coefficient: 200ppm; Tolerance: 5%
RS3 = RES: RES.,0.012 OHM,1%,1.5W,1206,LONG-SIDE TERM,METAL,SENSE,AEC-Q200; 9th Part Field: 0612; CLASS: DISCRETE; FPLIST: CR0612N,CR0612L,CR0612M; Inventory Qty: 0; Manufacturer: KOA SPEER; Manufacturer PN: WU732B15TTD12L0F; PART_NUMBER: 100-1869; Package Size: 1206,LONG-SIDE TERM; Rated Power: 1.5W; Temperature Coefficient: +/-100ppm; Tolerance: 1%
RS4 = RES: RES.,0.25 OHM,1%,1/2W,1206,SENSE,AEC-Q200; CLASS: DISCRETE; FPLIST: CR1206N,CR1206L,CR1206M; Inventory Qty: 0; Manufacturer: YAGEO; Manufacturer PN: PT1206FR-7W0R25L; PART_NUMBER: 100-1878; Package Size: 1206; Rated Power: 1/2W; Temperature Coefficient: +/-75ppm; Tolerance: 1%
TP13 = PAD_STYLE_C: TESTPOINT, PCB COPPER FEATURE; 10th Part Field: ______; 9th Part Field: FAULT2; CLASS: IO; FPLIST: PADSTYLE1,PADSTYLE2,PADSTYLE3,PADSTYLE4,PADSTYLE5,PADSTYLE6,PADSTYLE7,PADSTYLE8; Manufacturer: N/A; Manufacturer PN: N/A
TP16 = PAD_STYLE_C: TESTPOINT, PCB COPPER FEATURE; 9th Part Field: INTVCC; CLASS: IO; FPLIST: PADSTYLE1,PADSTYLE2,PADSTYLE3,PADSTYLE4,PADSTYLE5,PADSTYLE6,PADSTYLE7,PADSTYLE8; Manufacturer: N/A; Manufacturer PN: N/A
TP17 = PAD_STYLE_C: TESTPOINT, PCB COPPER FEATURE; 10th Part Field: ______; 9th Part Field: VC2; CLASS: IO; FPLIST: PADSTYLE1,PADSTYLE2,PADSTYLE3,PADSTYLE4,PADSTYLE5,PADSTYLE6,PADSTYLE7,PADSTYLE8; Manufacturer: N/A; Manufacturer PN: N/A
TP25 = PAD_STYLE_C: TESTPOINT, PCB COPPER FEATURE; 9th Part Field: VEXT2; CLASS: IO; FPLIST: PADSTYLE1,PADSTYLE2,PADSTYLE3,PADSTYLE4,PADSTYLE5,PADSTYLE6,PADSTYLE7,PADSTYLE8; Manufacturer: N/A; Manufacturer PN: N/A
TP26 = PAD_STYLE_C: TESTPOINT, PCB COPPER FEATURE; 10th Part Field: ____; 9th Part Field: VREF; CLASS: IO; FPLIST: PADSTYLE1,PADSTYLE2,PADSTYLE3,PADSTYLE4,PADSTYLE5,PADSTYLE6,PADSTYLE7,PADSTYLE8; Manufacturer: N/A; Manufacturer PN: N/A
TP27 = PAD_STYLE_C: TESTPOINT, PCB COPPER FEATURE; 10th Part Field: ____; 9th Part Field: SGND; CLASS: IO; FPLIST: PADSTYLE1,PADSTYLE2,PADSTYLE3,PADSTYLE4,PADSTYLE5,PADSTYLE6,PADSTYLE7,PADSTYLE8; Manufacturer: N/A; Manufacturer PN: N/A
U1 = LT8355-UFDM-1: IC,DUAL LED CONTROLLER,QFN-28,PRELIM.; CLASS: IC; Inventory Qty: 0; Manufacturer: ANALOG DEVICES; Manufacturer PN: LT8355IUFDM-1#WPBF; PART_NUMBER: LT8355IUFDM-1#WPBF; Package Size: 4mm x 5mm; Package Type: QFN-28
LB1 = BLANK_LABEL: LABEL SPEC, DEMO BOARD SERIAL NUMBER; Inventory Qty: 0; Manufacturer: BRADY; Manufacturer PN: THT-96-717-10; PART_NUMBER: 895-0154
MP1-MP4 = BLANK_MECHANICAL_PART: STANDOFF,NYLON,SNAP-ON,0.50"; CLASS: DISCRETE; Inventory Qty: 214842; Manufacturer: KEYSTONE; Manufacturer PN: 8833; PART_NUMBER: 763-0007
PCB1 = BLANK_PCB_PART: BOM Notes: REV02; CLASS: DISCRETE; Inventory Qty: 0; Manufacturer: ADI APPROVED SUPPLIER; Manufacturer PN: 600-EVAL-LT8355-1-AZ; PART_NUMBER: 600-EVAL-LT8355-1-AZ

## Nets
GND: C1.2 C2.2 C3.2 C5.2 C6.2 C7.2 C8.1 C9.2 C10.2 C11.2 C15.2 C18.2 C19.2 C20.2 C21.2 C22.2 C23.2 C24.2 C27.2 C28.2 C29.2 C30.2 C31.2 C32.2 C33.2 C34.1 C35.2 C36.2 C37.2 C39.2 C43.2 C45.2 C46.2 C47.2 C48.2 C49.2 C51.2 E8.1 E9.1 E13.1 J2.1 L2.3 L2.4 L4.3 L4.4 R3.1 R6.1 R10.2 R34.2 R37.2 R38.2 R40.2 R44.1 R47.2 RS1.1 RS3.1 TP10.1 TP23.1 TP27.1 U1.25(SENSEN2) U1.26(SENSEN1) U1.29(GND)
PVIN: C1.1 C2.1 C5.1 C6.1 C27.1 C28.1 C30.1 C45.1 E12.1 FB1.1 FB1.2 FB2.1 FB2.2 FB3.1 FB3.2 FB6.1 FB6.2 FB7.1 FB7.2 FB8.1 FB8.2 J1.1 L1.2 L3.2
VIN1: C3.1 C7.1 C12.1 C13.1 C16.1 C21.1 C22.1 C23.1 D2.2(A) FB5.2 L1.1 L2.2 R20.1 R33.2 U1.16(VIN)
VIN2: C29.1 C31.1 C32.1 C38.1 C40.1 C44.1 C48.1 D5.2(A) FB10.2 L3.1 L4.2 R53.1
FB1: Q1.3(C) R10.1 R11.1 R19.2 U1.4(FB1)
FB2: Q2.3(C) R45.2 R47.1 R48.2 U1.18(FB2)
INTVCC: C35.1 C46.1 R13.2 R32.1 R43.2 TP16.1 U1.22(INTVCC)
OUT1: C9.1 C10.1 C11.1 C12.2 C13.2 C14.2 C16.2 C24.1 D1.1 E10.1 R14.2 R21.1 R22.1 RS2.1 TP1.1 TP6.1 U1.3(ISP1)
OUT2: C36.1 C37.1 C38.2 C39.1 C40.2 C42.2 C44.2 D4.1 E11.1 R46.2 R51.1 R52.1 RS4.1 TP18.1 TP22.1 U1.19(ISP2)
SW1: C17.2 D1.2 D1.3 L2.1 M1.5(D)
SW2: C50.2 D4.2 D4.3 L4.1 M9.5(D)
VREF: C33.1 R1.2 R5.1 R19.1 R32.2 R35.2 R36.2 R39.1 R45.1 TP26.1 U1.14(VREF)
N1307564: R7.1 U1.28(GATE1)
N1307904: M1.1(S) M1.2(S) M1.3(S) RS1.2 U1.27(SENSEP1)
N1308680: C14.1 C25.1 M4.1(S) M4.2(S) M4.3(S) R12.1 R12.2 R25.1 RS2.2 TP7.1 TP9.1 U1.2(ISN1)
N1308972: R8.1 TP11.1 U1.5(VC1)
N1333307: R9.1 U1.1(PWMTG1)
N1363253: E14.1 R1.1 R3.2 U1.6(CTRL1)
N1479941: M1.4(G) R7.2
N16638500: E16.1 R5.2 R6.2 U1.10(PWM1)
N16681441: C15.1 E1.1 FB4.1
N16695910: R41.1 U1.23(GATE2)
N16695932: M9.1(S) M9.2(S) M9.3(S) RS3.2 U1.24(SENSEP2)
N16695964: C41.1 C42.1 M10.1(S) M10.2(S) M10.3(S) R50.1 R50.2 R59.1 RS4.2 TP20.1 TP21.1 U1.20(ISN2)
N16696008: R49.1 U1.21(PWMTG2)
N16696038: E15.1 R35.1 R37.1 U1.8(CTRL2)
N16696088: C43.1 E4.1 FB9.1
N16696102: M9.4(G) R41.2
N16696320: R43.1 TP13.1 U1.13(~{FAULT2})
N16718017: E18.1 R36.1 R38.1 U1.9(IADJ2)
N16718938: R42.1 TP17.1 U1.17(VC2)
N16723799: R13.1 TP5.1 U1.7(~{FAULT1})
N16756782: C20.1 FB4.2 M4.5(D) R25.2
N16782219: R40.1 U1.12(RT)
N16845459: C47.1 FB9.2 M10.5(D) R59.2
N16853950: C49.1 E3.1 FB10.1
N16890370: E17.1 R39.2 R44.2 U1.11(PWM2)
N16892391: C19.1 E2.1 FB5.1
N16901381: R33.1 R34.1 TP8.1 U1.15(EN/UVLO)
N16905516: C25.2 M4.4(G) R9.2
N16934518: Q1.1(B) R20.2 R21.2
N16934640: Q2.1(B) R51.2 R53.2
N16935856: R11.2 R14.1 TP3.1
N16936668: R46.1 R48.1 TP19.1
N16937846: Q2.2(E) R52.2
N16960106: C41.2 M10.4(G) R49.2
N16961856: C17.1 D2.1(C) D3.2(A)
N16961862: C18.1 D3.1(C) TP24.1
N16962058: C50.1 D5.1(C) D6.2(A)
N16962064: C51.1 D6.1(C) TP25.1
N16997024: C34.2 R42.2
N16998094: Q1.2(E) R22.2
N16998097: C8.2 R8.2

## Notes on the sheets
sheet 1
- 30VLED
- Vo2
- 1A
- V22
- V21
- I22
- I21
- 250kHz
- NOTES: UNLESS OTHERWISE SPECIFIED.
- 1. ALL RESISTORS  5%, 0402.
- 2. ALL CAPACITORS 0603.
sheet 2
- PCA ADDITIONAL PARTS
sheet 3
- IF L1 IS REMOVED, TIE INPUT TO VIN PIN
- PVIN
- 8V - 18V
- 450mA
  72VLED
- Vo1
- GND
- V12
- V11
- I12
- I11
- 7.5EN
- 6.2UVLO
- NOTES: UNLESS OTHERWISE SPECIFIED.
- 1. ALL RESISTORS  5%, 0402.
- 2. ALL CAPACITORS 0603.
